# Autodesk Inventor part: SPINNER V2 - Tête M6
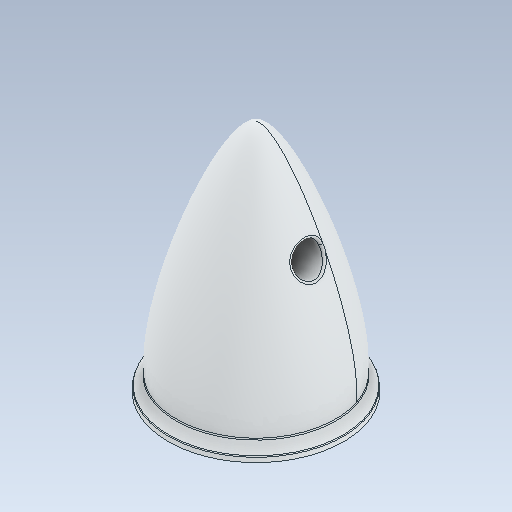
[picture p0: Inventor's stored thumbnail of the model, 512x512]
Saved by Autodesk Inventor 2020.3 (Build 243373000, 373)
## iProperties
Created: 2015-08
Part Number: SPINNER V2 - Tête M6
Material: Générique
Document SubType Name: Modeling
Designer: ficho
Density: 1 g/cm^3
Appearance: Par défaut
Author: ficho
Sending System: SolidWorks 2014
Last Author: Guillaume
Last Saved: 2015-08-26
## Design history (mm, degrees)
feature "Congé2"
node "Solide1"
